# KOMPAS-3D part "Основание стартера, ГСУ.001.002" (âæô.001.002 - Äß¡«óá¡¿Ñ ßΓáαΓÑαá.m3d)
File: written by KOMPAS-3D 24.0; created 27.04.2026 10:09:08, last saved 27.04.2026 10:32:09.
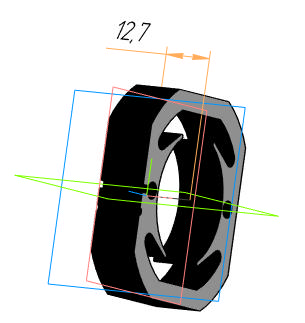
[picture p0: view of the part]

Document properties: Автор: User7; Полное имя файла: C:\Users\User7\Desktop\Двигатель мясорубки\ГСУ.001.002 - Основание стартера.m3d

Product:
- Body: Тело 1  | qty 1  | 64 such rows
    Масса: 0.000848
- Part/product: Основание стартера  | designation ГСУ.001.002
    Масса: 0.054294

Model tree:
1. Эскиз:1
2. Листовое тело:1
     Расстояние 1 = 10; Толщина листового тела = 0.1; Радиус сгиба = 5
3. Эскиз:2  (with: Грань.Листовое тело:1)
4. Элемент выдавливания:1
     Расстояние 2 = 10
5. Эскиз:3  (with: Грань.Листовое тело:1)
6. Элемент выдавливания:2
     Расстояние 2 = 10
7. Эскиз:4  (with: Грань.Листовое тело:1, Ребро.Элемент выдавливания:2, Ребро.Элемент выдавливания:1)
8. Элемент выдавливания:3
     Расстояние 2 = 10
9. Зеркальный массив:1
10. Экземпляр ( 1 )
11. Экземпляр ( 2 )  (with: Элемент выдавливания:3)
12. Эскиз:5  (with: Грань.Листовое тело:1)
13. Элемент выдавливания:4
     Расстояние 2 = 10
14. Эскиз:6  (with: Грань.Листовое тело:1, Вершина.Элемент выдавливания:2)
15. Элемент выдавливания:5
     Расстояние 2 = 10
16. Эскиз:7  (with: Грань.Листовое тело:1, Ребро.Элемент выдавливания:2)
17. Элемент выдавливания:6
     Расстояние 2 = 10
18. Массив по сетке:1  (2 pattern instances)
19. Тело 1  (62 pattern instances)
     Шаг 1 = 0.2; Угол раствора = 90; Шаг 2 = 10
20. Линейный размер:1  (with: Грань.Массив по сетке:1, Грань.Листовое тело:1)
     Значение = 12.7

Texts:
  ГСУ.001.002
